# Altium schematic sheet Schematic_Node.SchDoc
size 381 x 241 mm; SheetNumber: 1; SheetTotal: 1
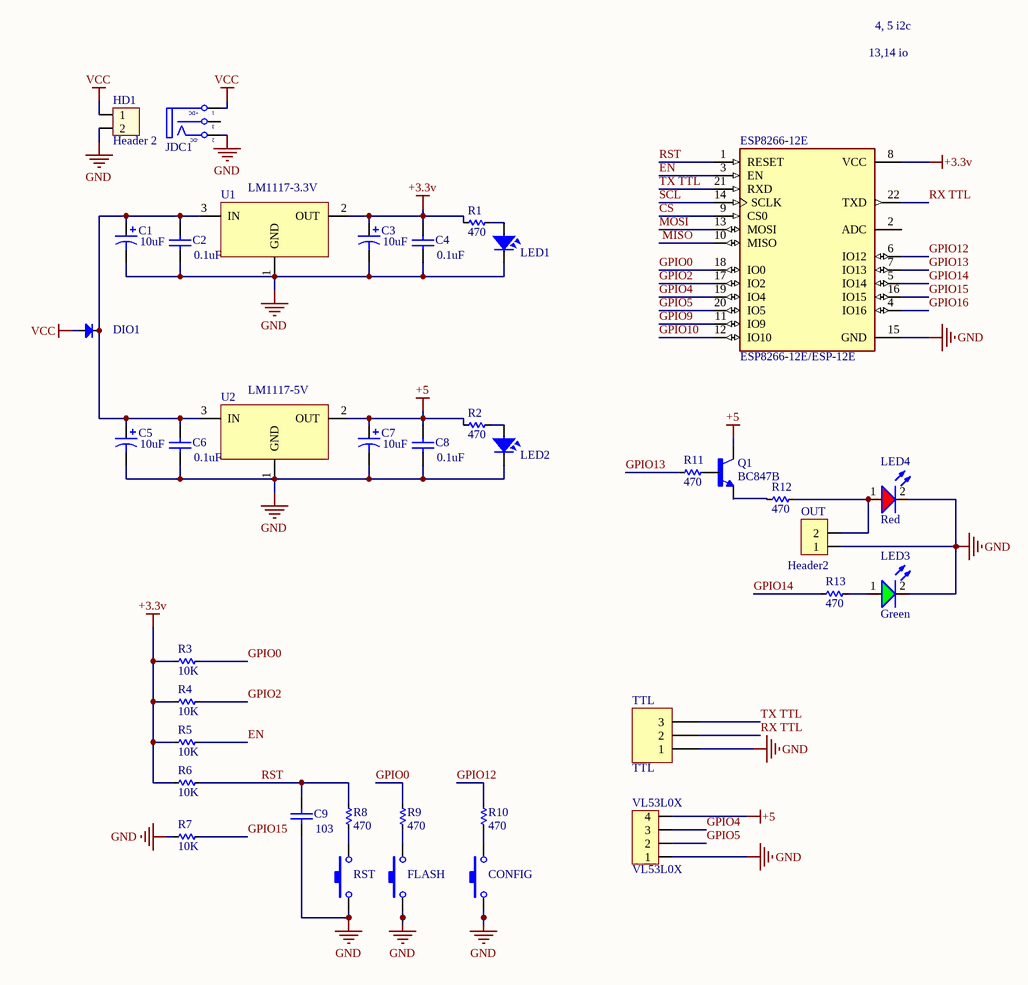
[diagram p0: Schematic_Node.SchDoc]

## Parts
C1  value 10uF  [C0805]  (hidden comment: Cap Pol3)
C2  value 0.1uF  [C1206]
C3  value 10uF  [C0805]  (hidden comment: Cap Pol3)
C4  value 0.1uF  [C1206]  (hidden comment: Cap Semi)
C5  value 10uF  [C0805]  (hidden comment: Cap Pol3)
C6  value 0.1uF  [C1206]
C7  value 10uF  [C0805]  (hidden comment: Cap Pol3)
C8  value 0.1uF  [C1206]  (hidden comment: Cap Semi)
C9  value 103  [C1206]  (hidden comment: Cap Semi)
CONFIG  SW-SMD  [SW-SMD]  (value not drawn)
DIO1  Diode SMD  [DIO-SMD-106]  (value not drawn)
ESP8266-12E  ESP8266-12E/ESP-12E  [XCVR_ESP8266-12E/ESP-12E]
FLASH  SW-SMD  [SW-SMD]  (value not drawn)
HD1  Header 2  [HED2]
JDC1  Jack DC  [DC-IN]  (value not drawn)
LED1  LED  [LED-1206-Red]  (value not drawn)
LED2  LED  [LED-1206-Red]  (value not drawn)
LED3  value Green  [LED-GREEN-0805]  (hidden comment: LED-Green)
LED4  value Red  [LED-RED-0805]  (hidden comment: LED-Red)
OUT  Header2  [HDR2]
Q1  BC847B  [SOT100P230X110-3N]
R1  470  [RES-SMD-1206]
R2  470  [RES-SMD-1206]
R3  10K  [RES-SMD-1206]
R4  10K  [RES-SMD-1206]
R5  10K  [RES-SMD-1206]
R6  10K  [RES-SMD-1206]
R7  10K  [RES-SMD-1206]
R8  470  [RES-SMD-1206]
R9  470  [RES-SMD-1206]
R10  470  [RES-SMD-1206]
R11  470  [RES-SMD-1206]
R12  470  [RES-SMD-1206]
R13  470  [RES-SMD-1206]
RST  SW-SMD  [SW-SMD]  (value not drawn)
TTL  TTL  [HDR1X3]
U1  LM1117-3.3V  [SOT223]
U2  LM1117-5V  [SOT223]
VL53L0X  VL53L0X  [HDR4]

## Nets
+3.3v: C3.1 C4.2 ESP8266-12E.8(VCC) R1.2 R3.2 R4.2 R5.2 R6.2 U1.2(OUT)
+5: C7.1 C8.2 Q1.3(C) R2.2 U2.2(OUT) VL53L0X.4
GND: C1.2 C2.1 C3.2 C4.1 C5.2 C6.1 C7.2 C8.1 C9.1 CONFIG.1 ESP8266-12E.15(GND) FLASH.1 HD1.2 JDC1.2(TN) LED1.2 LED2.2 LED3.2(K) LED4.2(K) OUT.1 R7.2 RST.1 TTL.1 U1.1(GND) U2.1(GND) VL53L0X.1
VCC: DIO1.1(A) HD1.1 JDC1.1(T)
CS: ESP8266-12E.9(CS0)
EN: ESP8266-12E.3(EN) R5.1
GPIO0: ESP8266-12E.18(IO0) R3.1 R9.1
GPIO2: ESP8266-12E.17(IO2) R4.1
GPIO4: ESP8266-12E.19(IO4) VL53L0X.3
GPIO5: ESP8266-12E.20(IO5) VL53L0X.2
GPIO9: ESP8266-12E.11(IO9)
GPIO10: ESP8266-12E.12(IO10)
GPIO12: ESP8266-12E.6(IO12) R10.1
GPIO13: ESP8266-12E.7(IO13) R11.2
GPIO14: ESP8266-12E.5(IO14) R13.2
GPIO15: ESP8266-12E.16(IO15) R7.1
GPIO16: ESP8266-12E.4(IO16)
MOSI: ESP8266-12E.13(MOSI)
RST: C9.2 ESP8266-12E.1(RESET) R6.1 R8.1
RX TTL: ESP8266-12E.22(TXD) TTL.2
SCL: ESP8266-12E.14(SCLK)
TX TTL: ESP8266-12E.21(RXD) TTL.3
MISO: ESP8266-12E.10(MISO)
NetC1_1: C1.1 C2.2 C5.1 C6.2 DIO1.2(K) U1.3(IN) U2.3(IN)
NetCONFIG_2: CONFIG.2 R10.2
NetFLASH_2: FLASH.2 R9.2
NetLED1_1: LED1.1 R1.1
NetLED2_1: LED2.1 R2.1
NetLED3_1: LED3.1(A) R13.1
NetLED4_1: LED4.1(A) OUT.2 R12.1
NetQ1_1: Q1.1(B) R11.1
NetQ1_2: Q1.2(E) R12.2
NetR8_2: R8.2 RST.2

Not connected (* = marked no-connect by the designer): ESP8266-12E 2(ADC); JDC1 3(S)

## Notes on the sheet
- 13,14 io
- 4, 5 i2c

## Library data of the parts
C1 C3 C5 C7 = Cap Pol3: Polarized Capacitor (Surface Mount)
C2 C4 C6 C8 C9 = Cap Semi: Capacitor (Semiconductor SIM Model)
CONFIG FLASH RST = SW-SMD: Switch
DIO1 = Diode SMD: Default Diode; Code - JEDEC: DO-214-AB; Value: 1N5007
ESP8266-12E = ESP8266-12E/ESP-12E: This WiFi module has a 32-bit MCU micro and clock speeds supporting 80 MHz or 160 MHz. Supports the RTOS and integrated Wi-Fi MAC/BB/RF/PA/LNA, and has an on-board antenna.; MF: AI-Thinker
HD1 = Hed2: Header 2 (Green)
JDC1 = Jack DC: Jack DC input; Value: Jac DC
LED1 LED2 = LED SMD: Value: LED 3 - 5 ly 2 Colour
LED3 = LED-Green: LED Green 2mA 3V 0805
LED4 = Led-Red: LED Red 2mA 1.8V 0805
OUT = Header2: Header IDC, 2 x 1 Pin Vertical 2.54mm Pitch (Non-Boxed, Male); Manufacturer: W¨¹rth Elektronik eiSos GmbH; partNo: 613002143121; ComponentLink1 Description: Manufacturer; ComponentLink2 Description: Datasheet; NoPins: 02
Q1 = BC847B: Bipolar (BJT) Transistor NPN 45V 100mA 100MHz 150mW Surface Mount SOT-523; MF: STMicroelectronics
R1-R13 = Res-SMD: Resistor; Manufacturer: Generic Components; Class: Passive
TTL = Header 3: Header, 3-Pin
U1 U2 = LM1117: 800mA Low-Dropout Linear Regulator
VL53L0X = Header4: Header IDC, 4 x 1 Pin Vertical 2.54mm Pitch (Non-Boxed, Male); Manufacturer: W¨¹rth Elektronik eiSos GmbH; partNo: 613002143121; ComponentLink1 Description: Manufacturer; ComponentLink2 Description: Datasheet; NoPins: 02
